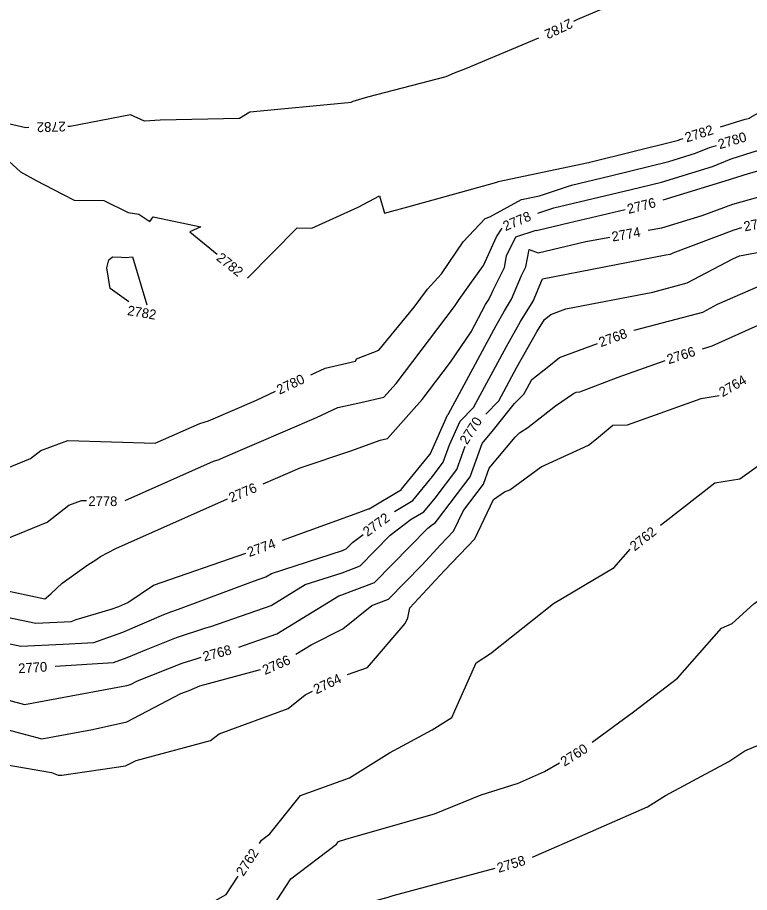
# Model space of a CAD drawing. Extents: x 1326424 to 1329294, y 1001359 to 1003823.
# Drawn here: x 1328473 to 1328623.5, y 1001626.3 to 1001806.2 of the extents above; entities that cross this region are included whole.
import ezdxf

# ---------------------------------------------------------------- set-up
doc = ezdxf.new("R2010")
doc.units = 0
doc.layers.add('Prop Rem of Exist Asph Pvmt', color=7, linetype='Continuous')
doc.layers.add('Scratch_Level_3', color=7, linetype='Continuous')

msp = doc.modelspace()

# ---------------------------------------------------------------- linework, layer by layer
at = {"layer": 'Prop Rem of Exist Asph Pvmt'}
for points in [[(1328533.31, 1001732.75), (1328536.23, 1001734.12), (1328542.48, 1001735.51), (1328542.67, 1001736.02), (1328547.29, 1001737.78), (1328554.54, 1001746.65), (1328557.28, 1001750.32), (1328560.14, 1001753.51), (1328564.62, 1001760.06), (1328569.17, 1001764.86), (1328570.09, 1001765.19), (1328576.64, 1001768.74), (1328580.29, 1001769.5), (1328586.86, 1001771.73), (1328594.88, 1001773.61), (1328606.85, 1001776.59), (1328612.35, 1001778.27), (1328615.26, 1001779.46), (1328616.65, 1001779.89)], [(1328462.77, 1001741.85), (1328462.41, 1001740.87), (1328458.57, 1001731.11), (1328458.15, 1001727.59), (1328459.73, 1001714.71), (1328459.72, 1001713.91), (1328459.99, 1001713.43), (1328461.16, 1001711.97), (1328467.97, 1001712.35), (1328475.73, 1001715.5), (1328477.83, 1001717.15), (1328483.41, 1001719.24), (1328501.3, 1001718.64), (1328510.51, 1001722.73), (1328512.3, 1001723.27), (1328512.74, 1001723.46), (1328522.14, 1001727.52), (1328526.06, 1001729.35)], [(1328591.16, 1001657.2), (1328599.59, 1001663.43), (1328608.67, 1001670.37), (1328617.7, 1001680.61), (1328619.92, 1001681.59), (1328624.35, 1001685.61), (1328639.72, 1001696.55), (1328647.87, 1001703.6), (1328666.51, 1001708.84), (1328671.34, 1001709.19), (1328673.43, 1001709.82)], [(1328495.2, 1001612.73), (1328496.2, 1001612.77), (1328508.69, 1001615.6), (1328515.34, 1001617.73), (1328525.51, 1001623.41), (1328529.21, 1001629.1), (1328538.59, 1001636.25), (1328538.99, 1001636.75), (1328540.69, 1001637.36), (1328558.76, 1001642.48), (1328568.33, 1001646.35), (1328575.49, 1001648.63), (1328575.75, 1001648.74), (1328581.33, 1001651.18), (1328584.42, 1001652.93)]]:
    msp.add_lwpolyline(points, dxfattribs=at)
at = {"layer": 'Scratch_Level_3'}
for points in [[(1328673.27, 1001855.17), (1328671.09, 1001853.07), (1328665.89, 1001849.34), (1328655.93, 1001842.73), (1328651.67, 1001839.36), (1328645.23, 1001834.48), (1328639.14, 1001830.8), (1328633.78, 1001827.16), (1328628.2, 1001823.97), (1328621.89, 1001819.83), (1328615.9, 1001816.66), (1328606.13, 1001813), (1328596.99, 1001809.54), (1328588.09, 1001805.78), (1328587.29, 1001805.38)], [(1328617.49, 1001783.68), (1328622.58, 1001785.26), (1328623.49, 1001785.52), (1328623.58, 1001785.64), (1328637.23, 1001793.31), (1328638.91, 1001794.13), (1328654, 1001801.9), (1328655.89, 1001803.09), (1328675.22, 1001815.13), (1328675.8, 1001815.43), (1328676.59, 1001815.85), (1328690.43, 1001823.33), (1328691.01, 1001823.67), (1328696.17, 1001829.06), (1328696.42, 1001829.22), (1328696.68, 1001829.58), (1328702.16, 1001835.29)], [(1328605.69, 1001768.67), (1328619.38, 1001772.86), (1328619.73, 1001773), (1328623.23, 1001774.12), (1328632.92, 1001776.86), (1328635.57, 1001777.3), (1328639.76, 1001779.41), (1328641.21, 1001781.12), (1328656.68, 1001788.34), (1328660.58, 1001789.83), (1328673.18, 1001796.72), (1328677.32, 1001798.63), (1328690.14, 1001805.42), (1328690.69, 1001805.68), (1328696.39, 1001807.08), (1328697.15, 1001807.32)], [(1328579.97, 1001765.97), (1328583.23, 1001767.08), (1328599.12, 1001770.8), (1328605.39, 1001772.36), (1328615.87, 1001775.57), (1328619.67, 1001777.11), (1328624.03, 1001778.51), (1328631.63, 1001780.67), (1328632.88, 1001782.36), (1328636.2, 1001784.23), (1328652.94, 1001792.36), (1328656.07, 1001793.98), (1328661.4, 1001797.32), (1328671.39, 1001802.8), (1328671.83, 1001803.03)], [(1328580.07, 1001801.93), (1328565.09, 1001795.61), (1328562.75, 1001794.74), (1328561.08, 1001793.97), (1328544.95, 1001789.81), (1328541.95, 1001788.88), (1328541.53, 1001788.73), (1328540.96, 1001788.65), (1328520.79, 1001786.74), (1328518.69, 1001785.42), (1328502.39, 1001785.05), (1328499.15, 1001784.85), (1328496.28, 1001786.19), (1328483.87, 1001783.8), (1328483.39, 1001783.79)], [(1328602.62, 1001762.43), (1328605.47, 1001762.93), (1328613.76, 1001765.47), (1328620.01, 1001767.82), (1328628.57, 1001770.24), (1328639.25, 1001772.03), (1328656.17, 1001780.53), (1328656.23, 1001780.6), (1328656.83, 1001780.88), (1328668.91, 1001785.48), (1328671.96, 1001787.15), (1328684.58, 1001792.97), (1328691.46, 1001796.62), (1328695.3, 1001798.43)], [(1328475.39, 1001783.55), (1328474.76, 1001783.53), (1328469.33, 1001784.72), (1328462.2, 1001786.6), (1328453.61, 1001785.68), (1328459.25, 1001783.07), (1328460, 1001779.98), (1328461.73, 1001776.11), (1328462.23, 1001775.68), (1328462.89, 1001774.78), (1328464.3, 1001774.72), (1328470.53, 1001777.34), (1328473.65, 1001774.45), (1328476.91, 1001772.67), (1328482.27, 1001769.89), (1328484.72, 1001768.64), (1328490.81, 1001768.56), (1328495.75, 1001766.08), (1328497.96, 1001765.75), (1328500.22, 1001764.25), (1328500.95, 1001765.17), (1328510.71, 1001763.17), (1328508.43, 1001762.1), (1328514.05, 1001757.53)], [(1328520.29, 1001752.59), (1328530.5, 1001762.93), (1328533.52, 1001762.88), (1328543.02, 1001767.16), (1328547.44, 1001769.51), (1328548.47, 1001765.95), (1328553.99, 1001767.49), (1328571.09, 1001772.17), (1328571.73, 1001772.4), (1328571.84, 1001772.46), (1328590.38, 1001776.35), (1328590.5, 1001776.39), (1328590.63, 1001776.42), (1328608.32, 1001780.82), (1328608.84, 1001780.98), (1328609.12, 1001781.09), (1328609.85, 1001781.32)], [(1328599.7, 1001741.88), (1328600.03, 1001741.94), (1328613.86, 1001745.62), (1328616.91, 1001747.23), (1328626.82, 1001751.58), (1328647.46, 1001755.48), (1328649.49, 1001755.78), (1328663, 1001759.65), (1328665.54, 1001760.15), (1328672.14, 1001762.78), (1328690.58, 1001769.83), (1328694.49, 1001771.55), (1328694.74, 1001771.65)], [(1328523.55, 1001710.33), (1328531.12, 1001713.6), (1328541.74, 1001717.2), (1328547.54, 1001719.29), (1328549.08, 1001719.64), (1328556.21, 1001727.63), (1328562.02, 1001735.31), (1328566.23, 1001741.55), (1328569.24, 1001747.17), (1328569.74, 1001748.03), (1328570.17, 1001748.74), (1328570.77, 1001750.13), (1328573.1, 1001754.8), (1328573.53, 1001757.18), (1328575.46, 1001761.12), (1328579.63, 1001762.45), (1328579.71, 1001762.42), (1328585.09, 1001763.71), (1328597.94, 1001766.72)], [(1328613.77, 1001738.07), (1328615.75, 1001738.66), (1328623.98, 1001742.37), (1328632.21, 1001745.99), (1328641.02, 1001747.66), (1328650.29, 1001749.02), (1328656.05, 1001750.67), (1328670.75, 1001753.59), (1328688.35, 1001760.61), (1328693.61, 1001762.08), (1328699.92, 1001764.86), (1328708.63, 1001768.11)], [(1328449.72, 1001764.82), (1328450.61, 1001763.93), (1328450.53, 1001762.39), (1328450.24, 1001749.05), (1328450.31, 1001749), (1328450.34, 1001748.9), (1328454.98, 1001744.41), (1328455.55, 1001742.72), (1328455.54, 1001742.01), (1328455.38, 1001741.56), (1328454.41, 1001739.11), (1328453.09, 1001728.1), (1328454.13, 1001719.72), (1328454.04, 1001712.78), (1328456.37, 1001708.64), (1328462.59, 1001700.83), (1328464.08, 1001698.96), (1328468.91, 1001695.83), (1328470.47, 1001698.9), (1328479.16, 1001702.42), (1328483.61, 1001705.94), (1328486.22, 1001706.91), (1328487.19, 1001706.88)], [(1328569.26, 1001724.66), (1328571.92, 1001727.37), (1328575.63, 1001734.29), (1328579.77, 1001741.55), (1328581.35, 1001744.12), (1328582.64, 1001745.14), (1328585.74, 1001746.32), (1328603.6, 1001749.75), (1328610.63, 1001751.62), (1328620.05, 1001756.57), (1328621.42, 1001757.18), (1328625.79, 1001758), (1328646.62, 1001761.47), (1328651.3, 1001763.83), (1328654.77, 1001764.83)], [(1328495.14, 1001706.87), (1328513.34, 1001714.97), (1328514.46, 1001715.3), (1328515.36, 1001715.7), (1328534.5, 1001723.95), (1328538.85, 1001725.99), (1328543.61, 1001727.05), (1328548.35, 1001728.13), (1328550.85, 1001730.94), (1328562.81, 1001746.75), (1328563.78, 1001748.19), (1328565.96, 1001751.29), (1328568.81, 1001755.17), (1328571.45, 1001761.11), (1328572.64, 1001762.87)], [(1328550.49, 1001704.62), (1328554.27, 1001706.88), (1328558.32, 1001711.84), (1328560.54, 1001714.79), (1328561.83, 1001718.33), (1328563.99, 1001723.18), (1328566.74, 1001725.98), (1328573.5, 1001738.58), (1328576.42, 1001743.71), (1328578.97, 1001747.85), (1328580.93, 1001752.43), (1328606.27, 1001757.38), (1328607.18, 1001757.55), (1328607.39, 1001757.61), (1328607.76, 1001757.81), (1328620.3, 1001762.52), (1328621.91, 1001762.98)], [(1328527.47, 1001698.75), (1328543.18, 1001704.42), (1328545.16, 1001705.16), (1328545.28, 1001705.2), (1328551.94, 1001709.18), (1328551.97, 1001709.19), (1328557.79, 1001716.31), (1328557.89, 1001716.52), (1328561.42, 1001724.44), (1328561.57, 1001724.59), (1328571.37, 1001742.88), (1328573.08, 1001745.87), (1328574.57, 1001748.29), (1328576.63, 1001753.11), (1328577.52, 1001754.9), (1328578.18, 1001758.49), (1328580.05, 1001757.82), (1328589.84, 1001760.16), (1328594.74, 1001761.03)], [(1328491.41, 1001754.74), (1328491.83, 1001756.33), (1328492.54, 1001756.96), (1328494.41, 1001756.94), (1328495.25, 1001756.81), (1328496.66, 1001757.01), (1328499.6, 1001747.1)], [(1328495.93, 1001747.72), (1328492.07, 1001750.44), (1328491.41, 1001754.74)], [(1328518.49, 1001676.72), (1328526.34, 1001679.45), (1328539.08, 1001687.28), (1328539.68, 1001687.47), (1328546.38, 1001690.04), (1328557.35, 1001701.23), (1328558.31, 1001701.95), (1328558.87, 1001702.29), (1328559.37, 1001702.9), (1328566.03, 1001711.76), (1328568.53, 1001718.62), (1328570.87, 1001721.4), (1328575.16, 1001726.8), (1328577.09, 1001728.76), (1328577.75, 1001730), (1328578.74, 1001731.74), (1328582.22, 1001734.5), (1328584.43, 1001736.28), (1328592.19, 1001739.16)], [(1328605.2, 1001701.85), (1328606.06, 1001702.52), (1328616.36, 1001710.54), (1328621.49, 1001711.35), (1328638.06, 1001723.21), (1328644.21, 1001725.98), (1328648.72, 1001726.64), (1328654.71, 1001729.4), (1328668.76, 1001732.56), (1328673.42, 1001733.02), (1328682.45, 1001735.8), (1328693.63, 1001737.58), (1328695.77, 1001738.94)], [(1328530.24, 1001675.29), (1328533.42, 1001677.24), (1328539.92, 1001680.52), (1328545.82, 1001685.27), (1328549.28, 1001686.6), (1328556.15, 1001693.61), (1328560.06, 1001697.82), (1328562.65, 1001700.56), (1328564.71, 1001704.83), (1328568.78, 1001710.24), (1328569.97, 1001713.52), (1328575.33, 1001719.89), (1328576.21, 1001720.8), (1328577.9, 1001721.87), (1328583.62, 1001726.37), (1328587.31, 1001728.9), (1328587.82, 1001729.13), (1328588.59, 1001729.22), (1328596.44, 1001732.27), (1328606.14, 1001735.65)], [(1328448.26, 1001726.86), (1328448.52, 1001724.73), (1328448.36, 1001711.65), (1328452.75, 1001703.85), (1328457.06, 1001698.43), (1328462.7, 1001691.36), (1328465.75, 1001689.38), (1328478.64, 1001686.7), (1328478.91, 1001686.87), (1328479.99, 1001687.77), (1328482.19, 1001689.86), (1328487.32, 1001693.51), (1328489.33, 1001694.8), (1328490.09, 1001695.35), (1328493.22, 1001696.99), (1328516.18, 1001707.2), (1328516.19, 1001707.2)], [(1328540.86, 1001671.11), (1328544.97, 1001672.57), (1328552.7, 1001681.62), (1328553.23, 1001682.76), (1328553.67, 1001684.8), (1328560.8, 1001692.5), (1328566.99, 1001699.04), (1328570.88, 1001707.1), (1328573.08, 1001708.64), (1328574.22, 1001709.05), (1328580.65, 1001713.81), (1328590.39, 1001718.23), (1328592.01, 1001719.55), (1328595.39, 1001722.4), (1328598.4, 1001722.42), (1328613.53, 1001727.85), (1328617.23, 1001728.44)], [(1328480.77, 1001672.84), (1328492.78, 1001673.58), (1328495.58, 1001674.58), (1328499.52, 1001676.27), (1328505.71, 1001678.72), (1328511.76, 1001680.71), (1328512.74, 1001680.97), (1328525.2, 1001685.31), (1328532.18, 1001689.59), (1328539.74, 1001692.05), (1328543.48, 1001693.48), (1328549.6, 1001699.73), (1328553.96, 1001703.03), (1328556.57, 1001704.59), (1328558.85, 1001707.37), (1328563.29, 1001713.28), (1328565.03, 1001718.06)], [(1328442.76, 1001716.8), (1328442.68, 1001710.52), (1328449.13, 1001699.06), (1328451.54, 1001696.04), (1328457.26, 1001688.86), (1328460.09, 1001685.51), (1328463.68, 1001684.43), (1328476.79, 1001681.7), (1328484.1, 1001682.02), (1328485.13, 1001682.4), (1328492.31, 1001684.56), (1328493.87, 1001685.11), (1328495.71, 1001685.9), (1328501, 1001689.46), (1328519.94, 1001696.06)], [(1328451.7, 1001686.83), (1328456.07, 1001681.66), (1328467.32, 1001678.29), (1328473.72, 1001676.95), (1328482.34, 1001677.32), (1328488.75, 1001677.72), (1328494.72, 1001679.84), (1328503.14, 1001683.45), (1328504.54, 1001684.01), (1328506.16, 1001684.54), (1328521.53, 1001690.29), (1328524.06, 1001691.17), (1328525.27, 1001691.91), (1328539.8, 1001696.63), (1328540.57, 1001696.92), (1328541.85, 1001698.22), (1328544.04, 1001699.88)], [(1328425.03, 1001698.13), (1328427.14, 1001696.65), (1328429.42, 1001691.26), (1328431.24, 1001690.52), (1328434.34, 1001685.36), (1328446.14, 1001676.19), (1328448.03, 1001673.95), (1328453.01, 1001672.46), (1328466.07, 1001667.24), (1328474.5, 1001664.98), (1328495.5, 1001668.86), (1328496.24, 1001669.03), (1328497.69, 1001669.79), (1328506.87, 1001673.43), (1328509.73, 1001674.37), (1328510.77, 1001674.65)], [(1328522.75, 1001636.39), (1328523.2, 1001637.08), (1328524.88, 1001638.36), (1328531.2, 1001646.27), (1328541.28, 1001649.87), (1328549.47, 1001655.04), (1328558.23, 1001659.71), (1328562.27, 1001662.28), (1328567.3, 1001673.49), (1328570.25, 1001675.45), (1328583.19, 1001685.7), (1328595.63, 1001693.13), (1328598.94, 1001696.88)], [(1328578.84, 1001633.58), (1328579.65, 1001633.93), (1328589.66, 1001638.31), (1328602.49, 1001643.9), (1328606.22, 1001646.27), (1328619.22, 1001653.2), (1328622.47, 1001655.44), (1328636.94, 1001661.52), (1328643.81, 1001663.77), (1328650.95, 1001669.38), (1328659.05, 1001675.39), (1328661.24, 1001677.71), (1328665.7, 1001680.1), (1328666.32, 1001680.54)], [(1328431.07, 1001678.93), (1328435.92, 1001675.16), (1328440.74, 1001670.68), (1328443.23, 1001668.37), (1328446.5, 1001666.7), (1328461.23, 1001662.25), (1328461.8, 1001662.14), (1328462.59, 1001662), (1328478.04, 1001657.86), (1328488.45, 1001659.78), (1328495.5, 1001661.41), (1328506.58, 1001667.23), (1328508.32, 1001667.85), (1328510.48, 1001668.78), (1328522.96, 1001672.11)], [(1328438.83, 1001661.26), (1328446.54, 1001657.32), (1328449.15, 1001656.53), (1328462.89, 1001653.93), (1328480, 1001650.99), (1328481.4, 1001650.39), (1328482.13, 1001650.4), (1328495.21, 1001652.36), (1328497.43, 1001653.47), (1328512.73, 1001657.55), (1328514.5, 1001658.91), (1328528.64, 1001664.11), (1328532.14, 1001666.97), (1328533.63, 1001667.69)], [(1328427.85, 1001634.19), (1328437.57, 1001626.62), (1328437.79, 1001626.47), (1328438.23, 1001626.24), (1328444.69, 1001625.22), (1328458.31, 1001626.58), (1328459.85, 1001622.18), (1328460.68, 1001621.87), (1328464.7, 1001621.47), (1328464.89, 1001621.45), (1328492.56, 1001618.75), (1328495.01, 1001618.83), (1328497.31, 1001619.35), (1328513.57, 1001624.56), (1328515.9, 1001625.86), (1328518.38, 1001629.68)], [(1328475.98, 1001605.92), (1328476.83, 1001605.95), (1328496.63, 1001606.51), (1328499.64, 1001606.76), (1328516.85, 1001610.31), (1328519.12, 1001611.39), (1328533.82, 1001620.24), (1328535.13, 1001620.97), (1328535.23, 1001621.12), (1328535.52, 1001621.34), (1328547.46, 1001624.89), (1328549.2, 1001625.35), (1328550.21, 1001625.65), (1328571.18, 1001631.29)]]:
    msp.add_lwpolyline(points, dxfattribs=at)

# ---------------------------------------------------------------- texts
at = {"layer": 'Prop Rem of Exist Asph Pvmt'}
for s, rotation, p in [('2780', 16.5913, (1328617.32, 1001779.09)), ('2780', 25.1074, (1328526.87, 1001728.62)), ('2760', 32.3534, (1328585.42, 1001652.14))]:
    msp.add_text(s, height=2, rotation=rotation, dxfattribs=at).set_placement(p)
at = {"layer": 'Scratch_Level_3'}
for s, rotation, p in [('2782', 205.5369, (1328586.51, 1001806.03)), ('2782', 181.673, (1328482.94, 1001784.78)), ('2782', 17.1895, (1328610.54, 1001780.49)), ('2776', 14.1233, (1328598.6, 1001765.79)), ('2778', 22.9616, (1328573.31, 1001762.25)), ('2772', 11.3581, (1328622.48, 1001762.21)), ('2774', 10.0754, (1328595.33, 1001760.11)), ('2782', 321.6249, (1328513.74, 1001756.46)), ('2782', 350.4307, (1328495.5, 1001745.03)), ('2768', 19.8983, (1328592.92, 1001738.4)), ('2766', 17.6114, (1328606.84, 1001734.89)), ('2764', 30.0003, (1328617.91, 1001728.09)), ('2770', 57.3865, (1328565.41, 1001718.22)), ('2776', 23.0421, (1328516.97, 1001706.43)), ('2778', 359.9461, (1328487.61, 1001705.75)), ('2772', 36.3049, (1328544.94, 1001699.37)), ('2762', 38.4155, (1328599.86, 1001696.4)), ('2774', 19.6482, (1328520.67, 1001695.25)), ('2768', 14.9982, (1328511.44, 1001673.79)), ('2766', 23.5581, (1328523.89, 1001671)), ('2770', 3.5426, (1328473.26, 1001671.37)), ('2764', 25.2999, (1328534.43, 1001667.02)), ('2762', 56.9498, (1328519.46, 1001629.5)), ('2758', 16.6451, (1328571.9, 1001630.34))]:
    msp.add_text(s, height=2, rotation=rotation, dxfattribs=at).set_placement(p)

doc.saveas('drawing.dxf')
